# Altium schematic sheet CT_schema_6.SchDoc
size 274 x 160 mm
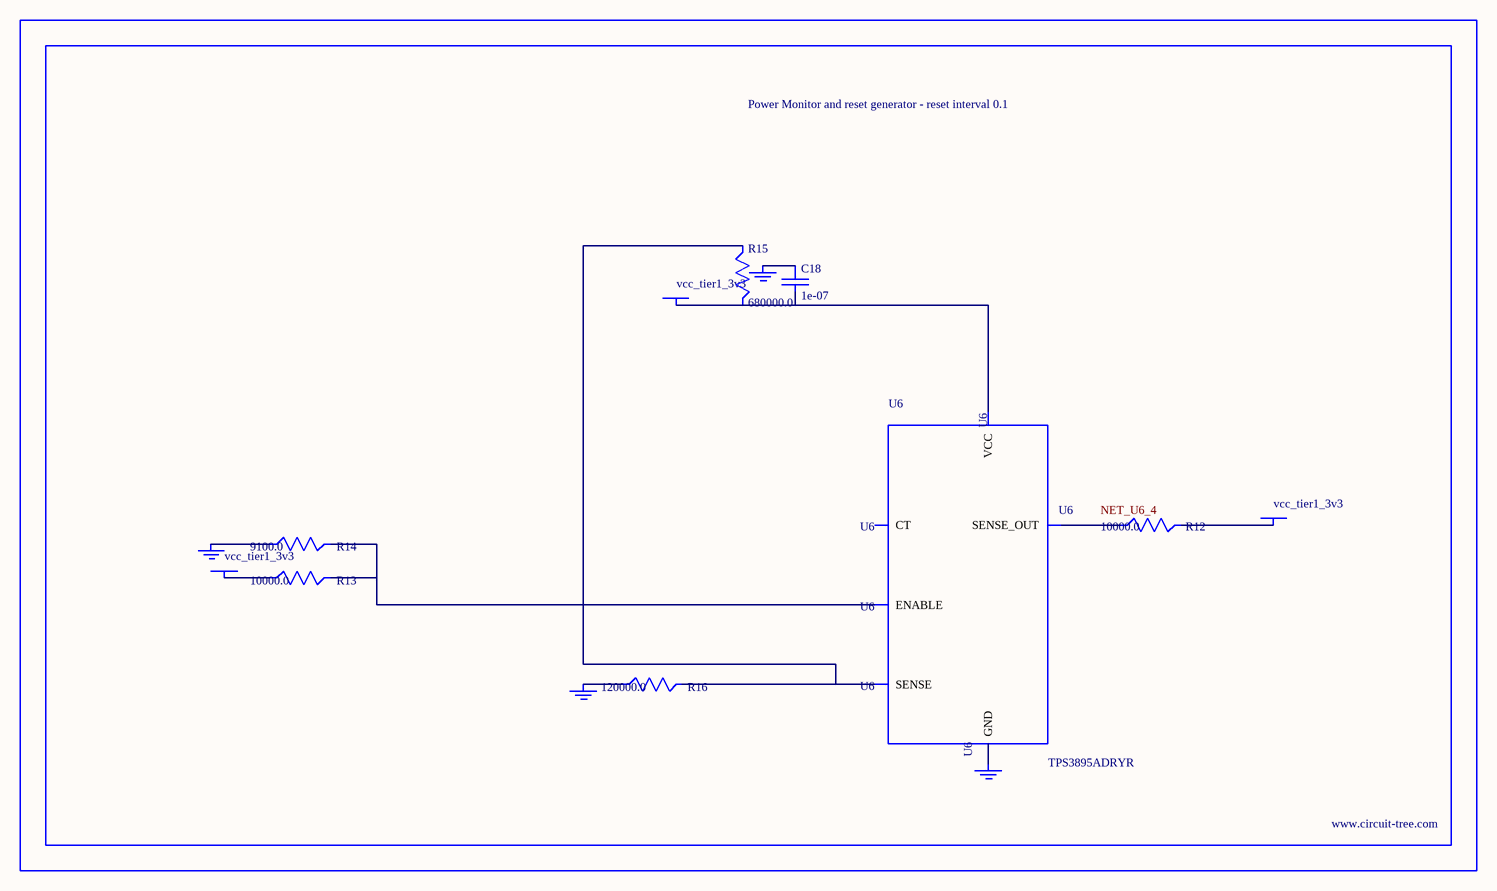
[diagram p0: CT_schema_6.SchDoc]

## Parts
BORDER5  (no value)
C18  1e-07  [C0402]
GND_INSTANCE_5_0  (no value)
GND_INSTANCE_5_1  (no value)
GND_INSTANCE_5_2  (no value)
GND_INSTANCE_5_3  (no value)
POWER_INSTANCE_5_0  vcc_tier1_3v3
POWER_INSTANCE_5_1  vcc_tier1_3v3
POWER_INSTANCE_5_2  vcc_tier1_3v3
R12  10000.0  [R0603]
R13  10000.0  [R0603]
R14  9100.0  [R0603]
R15  680000.0  [R0603]
R16  120000.0  [R0603]
U6  TPS3895ADRYR  [SON-6]

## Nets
NetC18_1: C18.1 GND_INSTANCE_5_2.0(GND)
NetC18_2: C18.2 POWER_INSTANCE_5_2.0(PWR) R15.2 U6.6(VCC)
NetGND_INSTANCE_5_0_0: GND_INSTANCE_5_0.0(GND) R14.1
NetGND_INSTANCE_5_1_0: GND_INSTANCE_5_1.0(GND) R16.1
NetGND_INSTANCE_5_3_0: GND_INSTANCE_5_3.0(GND) U6.2(GND)
NetPOWER_INSTANCE_5_0_0: POWER_INSTANCE_5_0.0(PWR) R13.1
NetPOWER_INSTANCE_5_1_0: POWER_INSTANCE_5_1.0(PWR) R12.2
NetR12_1: R12.1 U6.4(SENSE_OUT)
NetR13_2: R13.2 R14.2 U6.1(ENABLE)
NetR15_1: R15.1 R16.2 U6.3(SENSE)

Not connected (* = marked no-connect by the designer): U6 5(CT)

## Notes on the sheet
- Labels drawn without touching a wire or pin: NET_U6_4

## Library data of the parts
BORDER5 = BORDER_PAGE5
C18 = C0402C104K3RACTU
GND_INSTANCE_5_0-GND_INSTANCE_5_3 = GND
POWER_INSTANCE_5_0-POWER_INSTANCE_5_2 = PWR
R12 R13 = RC0603JR-0710KL
R14 = RC0603JR-079K1L
R15 = RC0603JR-07680KL
R16 = RC0603JR-07120KL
